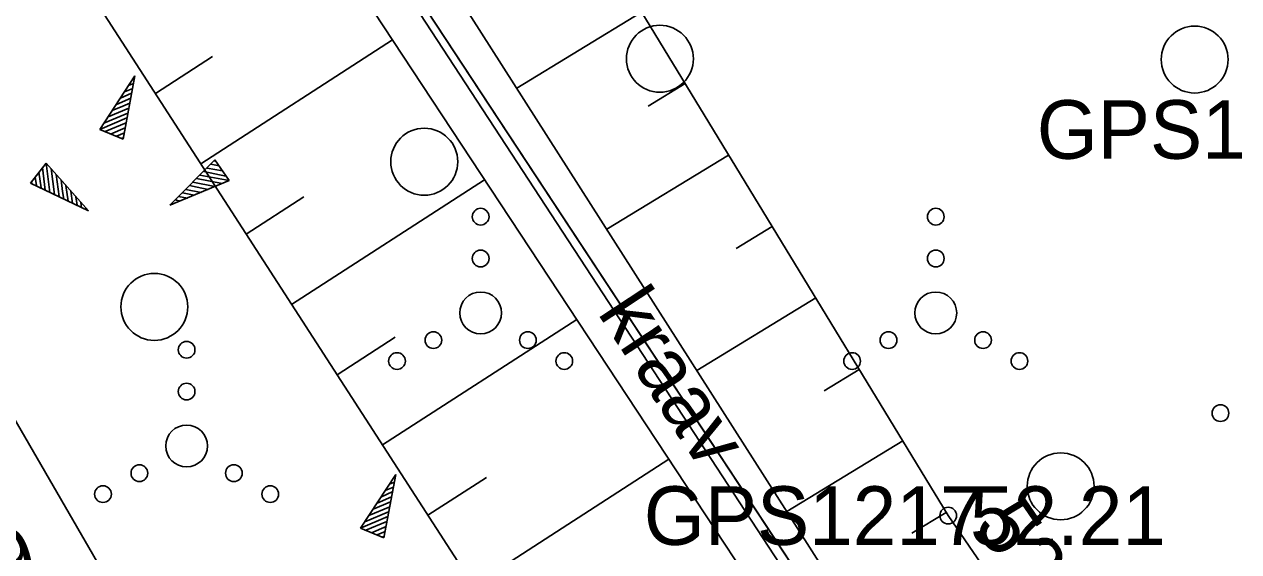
# Model space of a CAD drawing. Extents: x 551623 to 559850, y 6561220 to 6567135.
# Drawn here: x 555242.02 to 555256.53, y 6565120.82 to 6565127.12 of the extents above; entities that cross this region are included whole.
import ezdxf

# ---------------------------------------------------------------- set-up
doc = ezdxf.new("R2010")
doc.units = 0
for name, color, linetype in [('HALJASTUS', 7, 'Continuous'), ('KORGUS-EH2000', 7, 'Continuous'), ('MOOTKORG-EH2000', 7, 'Continuous'), ('MOOTMPUNKT', 7, 'Continuous'), ('MOOTNR', 7, 'Continuous'), ('PIIR', 7, 'Continuous'), ('RELJEEF', 7, 'Continuous'), ('VEEKOGU', 7, 'Continuous')]:
    doc.layers.add(name, color=color, linetype=linetype)

msp = doc.modelspace()

# ---------------------------------------------------------------- linework, layer by layer
at = {"layer": 'HALJASTUS'}
msp.add_lwpolyline([(555235.12, 6565151.155), (555232.135, 6565148.949), (555229.151, 6565146.49), (555228.521, 6565144.196), (555233.66, 6565136.637), (555246.422, 6565114.586), (555255.514, 6565098.946)], dxfattribs=at)
for centre, radius in [((555249.614, 6565126.709), 0.4), ((555256.007, 6565126.7), 0.4), ((555246.797, 6565125.479), 0.4), ((555247.471, 6565124.822), 0.1), ((555252.912, 6565124.822), 0.1), ((555247.471, 6565124.322), 0.1), ((555252.912, 6565124.322), 0.1), ((555243.57, 6565123.744), 0.4), ((555247.471, 6565123.672), 0.25), ((555252.912, 6565123.672), 0.25), ((555246.906, 6565123.347), 0.1), ((555248.036, 6565123.347), 0.1), ((555252.347, 6565123.347), 0.1), ((555253.477, 6565123.347), 0.1), ((555243.956, 6565123.232), 0.1), ((555246.471, 6565123.097), 0.1), ((555248.471, 6565123.097), 0.1), ((555251.912, 6565123.097), 0.1), ((555253.912, 6565123.097), 0.1), ((555243.956, 6565122.732), 0.1), ((555256.315, 6565122.475), 0.1), ((555243.956, 6565122.082), 0.25), ((555254.405, 6565121.6), 0.4), ((555243.391, 6565121.757), 0.1), ((555244.521, 6565121.757), 0.1), ((555242.956, 6565121.507), 0.1), ((555244.956, 6565121.507), 0.1)]:
    msp.add_circle(centre, radius, dxfattribs=at)
at = {"layer": 'KORGUS-EH2000'}
msp.add_circle((555253.061, 6565121.25), 0.1, dxfattribs=at)
at = {"layer": 'MOOTMPUNKT'}
msp.add_circle((555253.061, 6565121.25), 0.1, dxfattribs=at)
at = {"layer": 'PIIR'}
msp.add_lwpolyline([(555288.85, 6565092.31), (555275.41, 6565088.83), (555273.15, 6565087.34), (555239.11, 6565139), (555231.12, 6565150.64), (555225.89, 6565157.13), (555173.21, 6565166.35), (555173.84, 6565168.77), (555191.64, 6565237.48), (555195.28, 6565271.63), (555195.08, 6565294.61), (555205.15, 6565297.11), (555275.38, 6565300.17), (555292.52, 6565297.57)], dxfattribs=at)
msp.add_lwpolyline([(555172.58, 6565163.93), (555173.21, 6565166.35), (555225.89, 6565157.13), (555231.12, 6565150.64), (555239.11, 6565139), (555273.15, 6565087.34), (555275.41, 6565088.83), (555288.85, 6565092.31), (555289.83, 6565088.53), (555295.15, 6565083.63), (555324.46, 6565074.96), (555339.51, 6565058.58), (555337.29, 6565046.66), (555323.9, 6565035.68), (555298.08, 6565033.06), (555286.82, 6565022.41), (555284.62, 6565010.72), (555273.43, 6565013.07), (555140.74, 6565041.04)], close=True, dxfattribs=at)
at = {"layer": 'RELJEEF'}
for p, q in [((555249.395, 6565127.267), (555247.902, 6565126.357)), ((555244.125, 6565125.453), (555246.416, 6565126.934)), ((555243.583, 6565126.293), (555244.267, 6565126.736)), ((555242.917, 6565125.864), (555243.337, 6565126.504)), ((555243.337, 6565126.504), (555243.197, 6565125.749)), ((555243.212, 6565126.314), (555243.312, 6565126.354)), ((555243.262, 6565126.389), (555243.322, 6565126.414)), ((555243.312, 6565126.464), (555243.332, 6565126.474)), ((555249.916, 6565126.413), (555249.473, 6565126.143)), ((555243.117, 6565126.164), (555243.287, 6565126.239)), ((555243.167, 6565126.239), (555243.297, 6565126.299)), ((555242.967, 6565125.939), (555243.252, 6565126.059)), ((555243.017, 6565126.014), (555243.267, 6565126.119)), ((555243.067, 6565126.089), (555243.192, 6565126.144)), ((555243.192, 6565126.144), (555243.277, 6565126.179)), ((555242.917, 6565125.864), (555243.242, 6565126.004)), ((555242.982, 6565125.839), (555243.232, 6565125.944)), ((555242.917, 6565125.864), (555243.197, 6565125.749)), ((555242.917, 6565125.864), (555242.917, 6565125.864)), ((555243.047, 6565125.809), (555243.222, 6565125.884)), ((555243.117, 6565125.784), (555243.212, 6565125.824)), ((555243.182, 6565125.759), (555243.197, 6565125.764)), ((555242.276, 6565125.463), (555242.091, 6565125.223)), ((555242.276, 6565125.463), (555242.781, 6565124.893)), ((555242.276, 6565125.463), (555242.321, 6565125.113)), ((555242.276, 6565125.463), (555242.276, 6565125.463)), ((555243.755, 6565124.958), (555244.295, 6565125.503)), ((555244.305, 6565125.488), (555244.285, 6565125.488)), ((555244.465, 6565125.253), (555244.295, 6565125.503)), ((555250.436, 6565125.559), (555248.978, 6565124.671)), ((555242.191, 6565125.353), (555242.216, 6565125.168)), ((555242.231, 6565125.408), (555242.266, 6565125.138)), ((555242.336, 6565125.398), (555242.376, 6565125.088)), ((555242.396, 6565125.328), (555242.431, 6565125.063)), ((555244.465, 6565125.253), (555244.115, 6565125.318)), ((555244.425, 6565125.308), (555244.16, 6565125.363)), ((555244.385, 6565125.368), (555244.2, 6565125.403)), ((555244.345, 6565125.428), (555244.245, 6565125.448)), ((555242.781, 6565124.893), (555242.091, 6565125.223)), ((555242.101, 6565125.238), (555242.106, 6565125.218)), ((555242.146, 6565125.293), (555242.161, 6565125.193)), ((555242.456, 6565125.263), (555242.471, 6565125.123)), ((555242.511, 6565125.193), (555242.541, 6565125.008)), ((555244.465, 6565125.253), (555243.755, 6565124.958)), ((555244.08, 6565125.173), (555243.99, 6565125.193)), ((555244.295, 6565125.183), (555244.03, 6565125.233)), ((555244.38, 6565125.218), (555244.075, 6565125.278)), ((555244.215, 6565125.148), (555244.08, 6565125.173)), ((555244.465, 6565125.253), (555244.465, 6565125.253)), ((555245.211, 6565123.774), (555247.517, 6565125.264)), ((555242.471, 6565125.123), (555242.486, 6565125.033)), ((555242.571, 6565125.128), (555242.591, 6565124.983)), ((555242.631, 6565125.058), (555242.646, 6565124.958)), ((555243.965, 6565125.043), (555243.86, 6565125.063)), ((555244.045, 6565125.078), (555243.905, 6565125.108)), ((555244.13, 6565125.113), (555243.945, 6565125.148)), ((555244.668, 6565124.613), (555245.358, 6565125.059)), ((555242.691, 6565124.993), (555242.701, 6565124.928)), ((555242.751, 6565124.923), (555242.756, 6565124.903)), ((555243.795, 6565124.973), (555243.78, 6565124.978)), ((555243.88, 6565125.008), (555243.82, 6565125.023)), ((555250.956, 6565124.705), (555250.524, 6565124.442)), ((555251.477, 6565123.851), (555250.055, 6565122.985)), ((555246.297, 6565122.094), (555248.619, 6565123.595)), ((555245.754, 6565122.934), (555246.448, 6565123.383)), ((555251.997, 6565122.997), (555251.576, 6565122.741)), ((555252.517, 6565122.143), (555251.132, 6565121.299)), ((555247.383, 6565120.414), (555249.72, 6565121.925)), ((555246.035, 6565121.1), (555246.455, 6565121.74)), ((555246.455, 6565121.74), (555246.315, 6565120.985)), ((555246.43, 6565121.7), (555246.45, 6565121.71)), ((555246.84, 6565121.254), (555247.539, 6565121.706)), ((555246.33, 6565121.55), (555246.43, 6565121.59)), ((555246.38, 6565121.625), (555246.44, 6565121.65)), ((555246.235, 6565121.4), (555246.405, 6565121.475)), ((555246.285, 6565121.475), (555246.415, 6565121.535)), ((555246.31, 6565121.38), (555246.395, 6565121.415)), ((555246.085, 6565121.175), (555246.37, 6565121.295)), ((555246.135, 6565121.25), (555246.385, 6565121.355)), ((555246.185, 6565121.325), (555246.31, 6565121.38)), ((555253.038, 6565121.289), (555252.627, 6565121.039)), ((555246.035, 6565121.1), (555246.36, 6565121.24)), ((555246.1, 6565121.075), (555246.35, 6565121.18)), ((555246.165, 6565121.045), (555246.34, 6565121.12)), ((555246.035, 6565121.1), (555246.315, 6565120.985)), ((555246.035, 6565121.1), (555246.035, 6565121.1)), ((555246.235, 6565121.02), (555246.33, 6565121.06)), ((555246.3, 6565120.995), (555246.315, 6565121))]:
    msp.add_line(p, q, dxfattribs=at)
msp.add_lwpolyline([(555267.243, 6565100.718), (555264.574, 6565104.451), (555253.061, 6565121.25), (555242.65, 6565138.338), (555234.145, 6565148.829), (555233.386, 6565148.636), (555231.367, 6565148.23), (555230.85, 6565146.543), (555236.09, 6565137.882), (555248.799, 6565118.225), (555259.289, 6565103.411), (555261.934, 6565099.868)], dxfattribs=at)
at = {"layer": 'VEEKOGU'}
for points in [[(555265.45, 6565099.986), (555262.604, 6565103.817), (555251.937, 6565120.038), (555239.993, 6565138.74), (555233.721, 6565147.576), (555233.071, 6565146.869), (555239.071, 6565138.07), (555251.323, 6565119.495), (555261.764, 6565103.47), (555264.187, 6565099.861)], [(555239.299, 6565138.626), (555251.662, 6565119.733), (555262.176, 6565103.668)]]:
    msp.add_lwpolyline(points, dxfattribs=at)

# ---------------------------------------------------------------- texts
at = {"layer": 'KORGUS-EH2000'}
for s, rotation, p in [(' 52.21', 304.4233, (555253.206, 6565121.349)), (' 52.49', 17.9235, (555239.747, 6565119.693))]:
    msp.add_text(s, height=0.7, rotation=rotation, dxfattribs=at).set_placement(p)
at = {"layer": 'MOOTKORG-EH2000'}
msp.add_text(' 52.21', height=0.7, dxfattribs=at).set_placement((555253.061, 6565120.9))
at = {"layer": 'MOOTNR'}
for s, p in [('GPS1187 ', (555254.12, 6565125.514)), ('GPS1217 ', (555249.422, 6565120.9))]:
    msp.add_text(s, height=0.7, dxfattribs=at).set_placement(p)
at = {"layer": 'VEEKOGU'}
msp.add_text('kraav', height=0.7, rotation=303.3628, dxfattribs=at).set_placement((555248.858, 6565123.676))

doc.saveas('drawing.dxf')
